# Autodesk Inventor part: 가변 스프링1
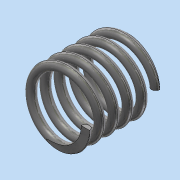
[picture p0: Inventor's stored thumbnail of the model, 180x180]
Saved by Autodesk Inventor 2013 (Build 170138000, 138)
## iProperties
Created: 2015-02
Part Number: 가변 스프링1
Material: 강철, 탄소
Document SubType Name: Modeling
Designer: dgall
Density: 7.87 g/cm^3
Mass: 18.7439 g
Surface Area: 32.3999 cm^2
Volume: 2.3817 cm^3
Author: dgall
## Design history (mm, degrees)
sketch "스케치1"
  geometry: L1 (11, 0)-(0, 0); L2 (0, 0)-(0, 25.358); L3 (0, 25.358)-(11, 25.358); C1 r 1.5 at (11, 0)
  constraints: 6 end point, 2 horizontal, 1 centre point, 1 coincident, 1 vertical, 1 vertical alignment
  dimensions: "d0" = 3 diameter of C1; "d2" = 25.35829 distance of L1.end L2.end (derived); "d4" = 22 diameter of C1.centre L2
feature "코일1" pitch "d5" = 10; turns "d7" = 5; dims "d6" = 25.35829 (= d2), "d8" = 0, angle "d9" = 90 deg, angle "d10" = 90 deg, "d11" = 0, "d12" = 0
sketch "스케치2"
  geometry: L1 (23.568, 37.992)-(-15.257, 37.992); L2 (-15.257, 37.992)-(-15.257, 25.358); L3 (-15.257, 25.358)-(23.568, 25.358); L4 (23.568, 25.358)-(23.568, 37.992); L5 (21.719, -8.918)-(-15.91, -8.918); L6 (-15.91, -8.918)-(-15.91, 0); L7 (-15.91, 0)-(21.719, 0); L8 (21.719, 0)-(21.719, -8.918); 5 further points
  constraints: 16 end point, 2 horizontal, 2 horizontal alignment, 2 point on line, 1 vertical alignment
extrude "돌출1" cut sketch "스케치2" stored distance "d13" = 10; taper "d14" = 0 deg
node "솔리드1"
node "투영된 루프1"
